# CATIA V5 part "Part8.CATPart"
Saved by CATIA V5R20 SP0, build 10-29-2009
Part number: 9FP1205M4
Revision: ANY
Definition: UNKNOWN
Nomenclature: 9FP1205M4
Source: Unknown
Bounding box of the stored display mesh (mm): x -5.752 to 5.752, y 0 to 5, z -5.9 to 5.9
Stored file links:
  C:\Users\Utente\Desktop\IO LAVORO\3D X SITO CF\CUMSA\3D files PW\pw060822\pw060822_injection\Part8.CATPart
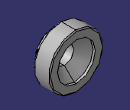
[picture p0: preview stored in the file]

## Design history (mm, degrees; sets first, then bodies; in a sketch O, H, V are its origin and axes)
Body1 "Redondeo2" (main body)
  Solid1: solid without history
